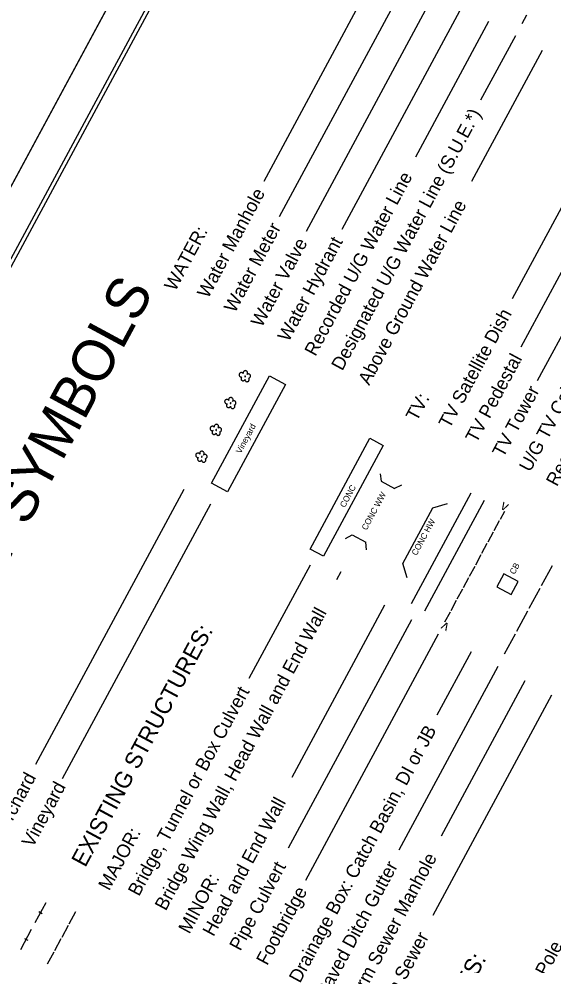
# Model space of a CAD drawing. Extents: x 1376167 to 1379209, y 761324 to 763997.
# Drawn here: x 1378067 to 1378417, y 762484 to 763105 of the extents above; entities that cross this region are included whole.
import ezdxf

# ---------------------------------------------------------------- set-up
doc = ezdxf.new("R2010")
doc.units = 0
for name, color, linetype in [('Sheet Cutting Line CELL', 7, 'Continuous'), ('Sheet Plot Border Inside CELL', 7, 'Continuous'), ('Sheet Plot Border Outside CELL', 7, 'Continuous'), ('Sheet Symbology CELL', 7, 'Continuous')]:
    doc.layers.add(name, color=color, linetype=linetype)

msp = doc.modelspace()

# ---------------------------------------------------------------- linework, layer by layer
at = {"layer": 'Sheet Cutting Line CELL'}
msp.add_line((1378241.03, 763327.89), (1377441.9, 761845.58), dxfattribs=at)
at = {"layer": 'Sheet Plot Border Inside CELL'}
msp.add_lwpolyline([(1378396.56, 761345.67), (1379187.39, 762812.58), (1378258.66, 763313.27), (1377467.83, 761846.37)], close=True, dxfattribs=at)
at = {"layer": 'Sheet Plot Border Outside CELL'}
msp.add_lwpolyline([(1378410.15, 761323.58), (1379209.29, 762805.89), (1378241.03, 763327.89), (1377441.9, 761845.58)], close=True, dxfattribs=at)
at = {"layer": 'Sheet Symbology CELL'}
for p, q in [((1378304.42, 763140.96), (1378227.36, 762998.02)), ((1378322.02, 763131.47), (1378237.54, 762974.75)), ((1378339.63, 763121.98), (1378255.14, 762965.26)), ((1378357.23, 763112.48), (1378278.56, 762966.55)), ((1378396.8, 763101.58), (1378399.88, 763107.3)), ((1378374.84, 763102.99), (1378326.86, 763013.99)), ((1378392.44, 763093.5), (1378369.66, 763051.24)), ((1378410.05, 763084.01), (1378363.68, 762998)), ((1378462.86, 763055.54), (1378390.33, 762921)), ((1378480.47, 763046.05), (1378395.98, 762889.33)), ((1378498.07, 763036.56), (1378406.8, 762867.26)), ((1378303.85, 762806.27), (1378304.42, 762801.3)), ((1378174.87, 762795.89), (1378077.62, 762615.5)), ((1378304.42, 762801.3), (1378313.22, 762796.56)), ((1378317.69, 762798.81), (1378313.22, 762796.56)), ((1378324.27, 762721.02), (1378363.42, 762793.64)), ((1378192.48, 762786.4), (1378095.23, 762606.01)), ((1378318.65, 762747.48), (1378338.23, 762783.79)), ((1378333.07, 762716.27), (1378372.22, 762788.89)), ((1378338.23, 762783.79), (1378347.81, 762786.66)), ((1378382.58, 762776.49), (1378385.42, 762781.77)), ((1378378.54, 762769.01), (1378382.1, 762775.61)), ((1378280.97, 762763.84), (1378285.44, 762766.09)), ((1378285.44, 762766.09), (1378294.24, 762761.35)), ((1378374.51, 762761.53), (1378378.07, 762768.13)), ((1378294.81, 762756.38), (1378294.24, 762761.35)), ((1378370.48, 762754.05), (1378374.03, 762760.65)), ((1378366.44, 762746.56), (1378370, 762753.17)), ((1378257.74, 762746.32), (1378217.67, 762672.01)), ((1378321.52, 762737.89), (1378318.65, 762747.48)), ((1378362.41, 762739.08), (1378365.97, 762745.68)), ((1378409.58, 762732.96), (1378416.7, 762746.16)), ((1378275.34, 762736.83), (1378278.18, 762742.1)), ((1378358.37, 762731.6), (1378361.93, 762738.2)), ((1378354.34, 762724.12), (1378357.9, 762730.72)), ((1378401.52, 762718), (1378408.63, 762731.2)), ((1378350.31, 762716.64), (1378353.87, 762723.24)), ((1378306.65, 762719.95), (1378245.77, 762607.02)), ((1378346.27, 762709.15), (1378349.83, 762715.76)), ((1378393.45, 762703.03), (1378400.57, 762716.24)), ((1378324.26, 762710.46), (1378243.49, 762560.65)), ((1378341.86, 762700.97), (1378254.79, 762539.47)), ((1378385.38, 762688.07), (1378392.5, 762701.27)), ((1378363.36, 762689.37), (1378340.97, 762647.83)), ((1378380.97, 762679.88), (1378315.98, 762559.34)), ((1378398.57, 762670.39), (1378343.68, 762568.57)), ((1378416.18, 762660.9), (1378338.26, 762516.37)), ((1378077.44, 762511.77), (1378084.56, 762524.97)), ((1378079.9, 762518.97), (1378082.1, 762517.78)), ((1378099.79, 762511.08), (1378104.07, 762519)), ((1378095.05, 762502.28), (1378099.32, 762510.2)), ((1378067.95, 762494.17), (1378075.07, 762507.37)), ((1378070.41, 762501.36), (1378072.61, 762500.17)), ((1378090.3, 762493.48), (1378094.57, 762501.4)), ((1378085.56, 762484.67), (1378089.83, 762492.6))]:
    msp.add_line(p, q, dxfattribs=at)
for points in [[(1378254.97, 763301.06), (1377543.15, 761980.71), (1378466.5, 761482.92), (1379178.32, 762803.27)], [(1378389.75, 762727.11), (1378394.31, 762735.57), (1378384.94, 762740.62), (1378380.38, 762732.16)]]:
    msp.add_lwpolyline(points, close=True, dxfattribs=at)
for points in [[(1378193.08, 762800.16), (1378231.04, 762870.58), (1378241.6, 762864.88), (1378203.64, 762794.46), (1378193.08, 762800.16)], [(1378213.88, 762871.93), (1378213.69, 762872.21), (1378213.45, 762872.4), (1378213.16, 762872.49), (1378212.87, 762872.59), (1378212.58, 762872.58), (1378212.29, 762872.57), (1378211.99, 762872.44), (1378211.74, 762872.29), (1378211.49, 762872.03), (1378211.37, 762871.81), (1378211.27, 762871.52), (1378211.22, 762871.21), (1378211.23, 762870.92), (1378211.29, 762870.6), (1378211.48, 762870.33), (1378211.65, 762870.12), (1378211.89, 762869.94), (1378212.16, 762869.8), (1378212.45, 762869.7), (1378212.74, 762869.71), (1378213.1, 762869.74), (1378212.85, 762869.59), (1378212.66, 762869.35), (1378212.52, 762869.09), (1378212.49, 762868.82), (1378212.46, 762868.56), (1378212.51, 762868.24), (1378212.59, 762867.97), (1378212.74, 762867.72), (1378212.94, 762867.56), (1378213.22, 762867.35), (1378213.47, 762867.27), (1378213.74, 762867.24), (1378214.05, 762867.3), (1378214.3, 762867.34), (1378214.55, 762867.48), (1378214.82, 762867.68), (1378214.98, 762867.87), (1378215.13, 762868.14), (1378215.1, 762867.87), (1378215.15, 762867.56), (1378215.26, 762867.33), (1378215.48, 762867.1), (1378215.69, 762866.87), (1378215.91, 762866.75), (1378216.2, 762866.65), (1378216.49, 762866.66), (1378216.78, 762866.68), (1378217.05, 762866.76), (1378217.3, 762866.91), (1378217.51, 762867.08), (1378217.65, 762867.34), (1378217.8, 762867.61), (1378217.87, 762867.85), (1378217.81, 762868.17), (1378217.8, 762868.46), (1378217.52, 762868.89)], [(1378217.52, 762868.89), (1378218.11, 762869.25), (1378218.35, 762869.47), (1378218.53, 762869.71), (1378218.63, 762870), (1378218.66, 762870.27), (1378218.65, 762870.56), (1378218.59, 762870.87), (1378218.44, 762871.12), (1378218.27, 762871.33), (1378218.05, 762871.56), (1378217.76, 762871.66), (1378217.48, 762871.76), (1378217.12, 762871.72), (1378216.87, 762871.69), (1378216.62, 762871.54), (1378216.34, 762871.34), (1378216.53, 762871.58), (1378216.7, 762871.89), (1378216.73, 762872.16), (1378216.74, 762872.5), (1378216.72, 762872.79), (1378216.6, 762873.08), (1378216.41, 762873.36), (1378216.17, 762873.54), (1378215.93, 762873.73), (1378215.64, 762873.83), (1378215.33, 762873.88), (1378215.01, 762873.82), (1378214.67, 762873.72), (1378214.42, 762873.57), (1378214.19, 762873.36), (1378214.01, 762873.12), (1378213.86, 762872.85), (1378213.81, 762872.54), (1378213.82, 762872.25), (1378213.88, 762871.93)], [(1378215.02, 762870.36), (1378214.95, 762870.22), (1378214.94, 762870.11), (1378214.94, 762870), (1378215.07, 762869.93), (1378215.16, 762869.88), (1378215.29, 762869.92), (1378215.37, 762870.05), (1378215.41, 762870.14), (1378215.37, 762870.28), (1378215.26, 762870.39), (1378215.15, 762870.4), (1378215.02, 762870.36)], [(1378204.39, 762854.33), (1378204.2, 762854.6), (1378203.96, 762854.79), (1378203.67, 762854.89), (1378203.38, 762854.99), (1378203.09, 762854.97), (1378202.8, 762854.96), (1378202.5, 762854.84), (1378202.25, 762854.69), (1378202, 762854.43), (1378201.88, 762854.21), (1378201.78, 762853.92), (1378201.73, 762853.61), (1378201.74, 762853.32), (1378201.8, 762853), (1378201.99, 762852.73), (1378202.16, 762852.52), (1378202.4, 762852.33), (1378202.67, 762852.19), (1378202.96, 762852.09), (1378203.25, 762852.11), (1378203.61, 762852.14), (1378203.35, 762851.99), (1378203.17, 762851.75), (1378203.03, 762851.49), (1378203, 762851.22), (1378202.96, 762850.95), (1378203.02, 762850.64), (1378203.1, 762850.36), (1378203.25, 762850.11), (1378203.45, 762849.95), (1378203.73, 762849.74), (1378203.98, 762849.67), (1378204.24, 762849.64), (1378204.56, 762849.69), (1378204.81, 762849.73), (1378205.06, 762849.88), (1378205.33, 762850.07), (1378205.49, 762850.27), (1378205.64, 762850.53), (1378205.61, 762850.27), (1378205.66, 762849.95), (1378205.77, 762849.72), (1378205.98, 762849.49), (1378206.2, 762849.26), (1378206.42, 762849.14), (1378206.71, 762849.05), (1378207, 762849.06), (1378207.29, 762849.07), (1378207.56, 762849.15), (1378207.81, 762849.3), (1378208.02, 762849.48), (1378208.16, 762849.74), (1378208.3, 762850), (1378208.38, 762850.25), (1378208.32, 762850.56), (1378208.31, 762850.85), (1378208.03, 762851.29)], [(1378208.03, 762851.29), (1378208.62, 762851.65), (1378208.85, 762851.87), (1378209.04, 762852.11), (1378209.14, 762852.39), (1378209.17, 762852.66), (1378209.16, 762852.95), (1378209.1, 762853.27), (1378208.95, 762853.52), (1378208.78, 762853.72), (1378208.56, 762853.96), (1378208.27, 762854.05), (1378207.99, 762854.15), (1378207.63, 762854.12), (1378207.38, 762854.08), (1378207.13, 762853.93), (1378206.85, 762853.74), (1378207.04, 762853.98), (1378207.21, 762854.29), (1378207.24, 762854.56), (1378207.25, 762854.89), (1378207.23, 762855.18), (1378207.11, 762855.48), (1378206.92, 762855.75), (1378206.68, 762855.94), (1378206.44, 762856.12), (1378206.15, 762856.22), (1378205.84, 762856.28), (1378205.52, 762856.22), (1378205.18, 762856.12), (1378204.93, 762855.97), (1378204.7, 762855.75), (1378204.51, 762855.51), (1378204.37, 762855.25), (1378204.32, 762854.94), (1378204.33, 762854.64), (1378204.39, 762854.33)], [(1378205.53, 762852.75), (1378205.45, 762852.62), (1378205.45, 762852.51), (1378205.45, 762852.4), (1378205.58, 762852.32), (1378205.67, 762852.28), (1378205.8, 762852.32), (1378205.87, 762852.45), (1378205.92, 762852.54), (1378205.88, 762852.67), (1378205.77, 762852.79), (1378205.66, 762852.79), (1378205.53, 762852.75)], [(1378194.9, 762836.73), (1378194.7, 762837), (1378194.46, 762837.19), (1378194.18, 762837.28), (1378193.89, 762837.38), (1378193.6, 762837.37), (1378193.31, 762837.36), (1378193.01, 762837.23), (1378192.76, 762837.08), (1378192.51, 762836.82), (1378192.39, 762836.6), (1378192.29, 762836.31), (1378192.24, 762836), (1378192.25, 762835.71), (1378192.31, 762835.4), (1378192.5, 762835.12), (1378192.67, 762834.91), (1378192.91, 762834.73), (1378193.18, 762834.59), (1378193.46, 762834.49), (1378193.76, 762834.5), (1378194.11, 762834.53), (1378193.86, 762834.39), (1378193.68, 762834.15), (1378193.54, 762833.88), (1378193.5, 762833.61), (1378193.47, 762833.35), (1378193.53, 762833.03), (1378193.61, 762832.76), (1378193.76, 762832.51), (1378193.96, 762832.35), (1378194.24, 762832.14), (1378194.49, 762832.06), (1378194.75, 762832.03), (1378195.07, 762832.09), (1378195.32, 762832.13), (1378195.57, 762832.28), (1378195.84, 762832.47), (1378196, 762832.66), (1378196.15, 762832.93), (1378196.11, 762832.66), (1378196.17, 762832.35), (1378196.28, 762832.12), (1378196.49, 762831.89), (1378196.71, 762831.66), (1378196.93, 762831.54), (1378197.22, 762831.44), (1378197.51, 762831.45), (1378197.8, 762831.47), (1378198.07, 762831.55), (1378198.32, 762831.7), (1378198.53, 762831.87), (1378198.67, 762832.13), (1378198.81, 762832.4), (1378198.89, 762832.64), (1378198.83, 762832.96), (1378198.82, 762833.25), (1378198.54, 762833.68)], [(1378198.54, 762833.68), (1378199.13, 762834.04), (1378199.36, 762834.26), (1378199.55, 762834.5), (1378199.65, 762834.79), (1378199.68, 762835.06), (1378199.67, 762835.35), (1378199.61, 762835.66), (1378199.46, 762835.91), (1378199.29, 762836.12), (1378199.07, 762836.35), (1378198.78, 762836.45), (1378198.49, 762836.55), (1378198.14, 762836.51), (1378197.89, 762836.48), (1378197.64, 762836.33), (1378197.36, 762836.13), (1378197.55, 762836.38), (1378197.72, 762836.68), (1378197.75, 762836.95), (1378197.76, 762837.29), (1378197.74, 762837.58), (1378197.62, 762837.87), (1378197.42, 762838.15), (1378197.18, 762838.33), (1378196.94, 762838.52), (1378196.66, 762838.62), (1378196.34, 762838.67), (1378196.03, 762838.61), (1378195.69, 762838.51), (1378195.44, 762838.36), (1378195.21, 762838.15), (1378195.02, 762837.91), (1378194.88, 762837.64), (1378194.83, 762837.33), (1378194.84, 762837.04), (1378194.9, 762836.73)], [(1378196.03, 762835.15), (1378195.96, 762835.01), (1378195.96, 762834.9), (1378195.96, 762834.79), (1378196.09, 762834.72), (1378196.18, 762834.67), (1378196.31, 762834.71), (1378196.38, 762834.85), (1378196.43, 762834.93), (1378196.39, 762835.07), (1378196.28, 762835.18), (1378196.17, 762835.19), (1378196.03, 762835.15)], [(1378257.75, 762756.88), (1378296.9, 762829.5), (1378305.7, 762824.75), (1378266.55, 762752.13), (1378257.75, 762756.88)], [(1378189.05, 762816.08), (1378189.64, 762816.44), (1378189.87, 762816.66), (1378190.06, 762816.9), (1378190.16, 762817.18), (1378190.19, 762817.45), (1378190.17, 762817.74), (1378190.12, 762818.06), (1378189.97, 762818.31), (1378189.8, 762818.52), (1378189.58, 762818.75), (1378189.29, 762818.84), (1378189, 762818.94), (1378188.64, 762818.91), (1378188.4, 762818.87), (1378188.15, 762818.72), (1378187.87, 762818.53), (1378188.06, 762818.77), (1378188.22, 762819.08), (1378188.26, 762819.35), (1378188.27, 762819.68), (1378188.25, 762819.97), (1378188.13, 762820.27), (1378187.93, 762820.54), (1378187.69, 762820.73), (1378187.45, 762820.91), (1378187.17, 762821.01), (1378186.85, 762821.07), (1378186.54, 762821.01), (1378186.2, 762820.91), (1378185.95, 762820.76), (1378185.72, 762820.54), (1378185.53, 762820.3), (1378185.39, 762820.04), (1378185.34, 762819.73), (1378185.35, 762819.44), (1378185.41, 762819.12)], [(1378185.41, 762819.12), (1378185.21, 762819.4), (1378184.97, 762819.58), (1378184.69, 762819.68), (1378184.4, 762819.78), (1378184.11, 762819.76), (1378183.82, 762819.75), (1378183.52, 762819.63), (1378183.27, 762819.48), (1378183.02, 762819.22), (1378182.9, 762819), (1378182.8, 762818.71), (1378182.74, 762818.4), (1378182.76, 762818.11), (1378182.82, 762817.79), (1378183.01, 762817.52), (1378183.18, 762817.31), (1378183.42, 762817.12), (1378183.69, 762816.98), (1378183.97, 762816.88), (1378184.26, 762816.9), (1378184.62, 762816.93), (1378184.37, 762816.78), (1378184.19, 762816.54), (1378184.04, 762816.28), (1378184.01, 762816.01), (1378183.98, 762815.74), (1378184.04, 762815.43), (1378184.12, 762815.16), (1378184.27, 762814.91), (1378184.47, 762814.74), (1378184.75, 762814.53), (1378184.99, 762814.46), (1378185.26, 762814.43), (1378185.58, 762814.48), (1378185.82, 762814.52), (1378186.08, 762814.67), (1378186.35, 762814.86), (1378186.51, 762815.06), (1378186.65, 762815.32), (1378186.62, 762815.06), (1378186.68, 762814.74), (1378186.79, 762814.51), (1378187, 762814.28), (1378187.22, 762814.05), (1378187.44, 762813.93), (1378187.73, 762813.84), (1378188.02, 762813.85), (1378188.31, 762813.86), (1378188.58, 762813.94), (1378188.83, 762814.09), (1378189.04, 762814.27), (1378189.18, 762814.53), (1378189.32, 762814.79), (1378189.4, 762815.04), (1378189.34, 762815.35), (1378189.33, 762815.64), (1378189.05, 762816.08)], [(1378186.54, 762817.54), (1378186.47, 762817.41), (1378186.47, 762817.3), (1378186.47, 762817.19), (1378186.6, 762817.12), (1378186.69, 762817.07), (1378186.82, 762817.11), (1378186.89, 762817.24), (1378186.94, 762817.33), (1378186.9, 762817.46), (1378186.79, 762817.58), (1378186.68, 762817.58), (1378186.54, 762817.54)]]:
    msp.add_lwpolyline(points, dxfattribs=at)

# ---------------------------------------------------------------- texts
for s, height, rotation, p in [('Designated U/G Water Line (S.U.E.*)', 8.75, 61.67024, (1378278.89, 762873.32)), ('Recorded U/G Water Line', 8.75, 61.67024, (1378261.29, 762882.81)), ('Water Manhole', 8.75, 61.67024, (1378190.87, 762920.77)), ('Above Ground Water Line', 8.75, 61.67024, (1378296.5, 762863.82)), ('Water Meter', 8.75, 61.67024, (1378208.47, 762911.28)), ('WATER:', 8.75, 61.67024, (1378169.34, 762925.51)), ('Water Valve', 8.75, 61.67024, (1378226.08, 762901.79)), ('Water Hydrant', 8.75, 61.67024, (1378243.68, 762892.3)), ('CONVENTIONAL  PLAN SHEET SYMBOLS', 27.2003, 61.67024, (1377814.01, 762292.51)), ('U/G TV Cable Hand Hole', 8.75, 61.67024, (1378402.12, 762806.88)), ('TV Satellite Dish', 8.75, 61.67024, (1378349.31, 762835.35)), ('Recorded U/G TV Cable', 8.75, 61.67024, (1378419.73, 762797.39)), ('TV Pedestal', 8.75, 61.67024, (1378366.91, 762825.86)), ('TV Tower', 8.75, 61.67024, (1378384.52, 762816.37)), ('TV:', 8.75, 61.67024, (1378327.78, 762840.09)), ('Vineyard', 4, 61.67026, (1378212.37, 762819.1)), ('CONC', 4, 61.67024, (1378280.57, 762783.7)), ('CONC WW', 4, 61.67026, (1378294.86, 762768.82)), ('v', 6.6, 331.91109, (1378382.13, 762783.54)), ('CONC HW', 4, 61.67024, (1378327.63, 762752.21)), ('CB', 4, 61.67024, (1378391.92, 762739.86)), ('Bridge Wing Wall, Head Wall and End Wall', 8.75, 61.67024, (1378163.1, 762519.05)), ('v', 6.6, 151.42939, (1378349.56, 762707.37)), ('EXISTING STRUCTURES:', 11, 61.67024, (1378110.29, 762547.52)), ('Bridge, Tunnel or Box Culvert', 8.75, 61.67024, (1378145.5, 762528.54)), ('Drainage Box: Catch Basin, DI or JB', 8.75, 61.67024, (1378251.12, 762471.61)), ('Orchard', 8.75, 61.67024, (1378058.25, 762570.03)), ('Vineyard', 8.75, 61.67024, (1378075.85, 762560.53)), ('Head and End Wall', 8.75, 61.67024, (1378194.41, 762502.17)), ('MAJOR:', 8.75, 61.67024, (1378126.01, 762532.2)), ('Storm Sewer Manhole', 8.75, 61.67024, (1378286.34, 762452.62)), ('Pipe Culvert', 8.75, 61.67024, (1378212, 762492.68)), ('Paved Ditch Gutter', 8.75, 61.67024, (1378268.73, 762462.11)), ('MINOR:', 8.75, 61.67024, (1378178.56, 762503.87)), ('Footbridge', 8.75, 61.67024, (1378229.61, 762483.2)), ('Storm Sewer', 8.75, 61.67024, (1378303.94, 762443.13)), ('Existing Power Pole', 8.75, 61.67024, (1378374.35, 762405.17)), ('Proposed Power Pole', 8.75, 61.67024, (1378391.96, 762395.68)), ('Existing Joint Use Pole', 8.75, 61.67024, (1378409.55, 762386.2)), ('UTILITIES:', 11, 61.67024, (1378339.15, 762424.14))]:
    msp.add_text(s, height=height, rotation=rotation, dxfattribs=at).set_placement(p)

doc.saveas('drawing.dxf')
